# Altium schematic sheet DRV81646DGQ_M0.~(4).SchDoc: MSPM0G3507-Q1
size 431 x 279 mm; Date: Not shown in title block; ApprovedBy: Not shown in title block; CheckedBy: Not shown in title block; Author: Not shown in title block; CompanyName: Not shown in title block; DrawnBy: Mojtaba Afshar; Engineer: Not shown in title block; Organization: Not shown in title block; Address1: Not shown in title block; Address2: Not shown in title block; Address3: Not shown in title block; Address4: Not shown in title block; DocumentNumber: 1; Revision: Use project parameter SCH_Rev; SheetNumber: 2; SheetTotal: 5; PageSetup: Record=PageOptions¦CenterHorizontal=True¦CenterVertical=True¦PrintScale=1.00¦XCorrection=1.00¦YCorrection=1.00¦PrintKind=0¦BorderSize=5000000¦LeftOffset=0¦BottomOffset=0¦Orientation=2¦PaperLength=1000¦PaperWidth=1000¦Scale=100¦PaperSource=15¦PrintQuality=600¦MediaType=1¦DitherType=10¦PaperKind=Letter¦PrintScaleMode=1
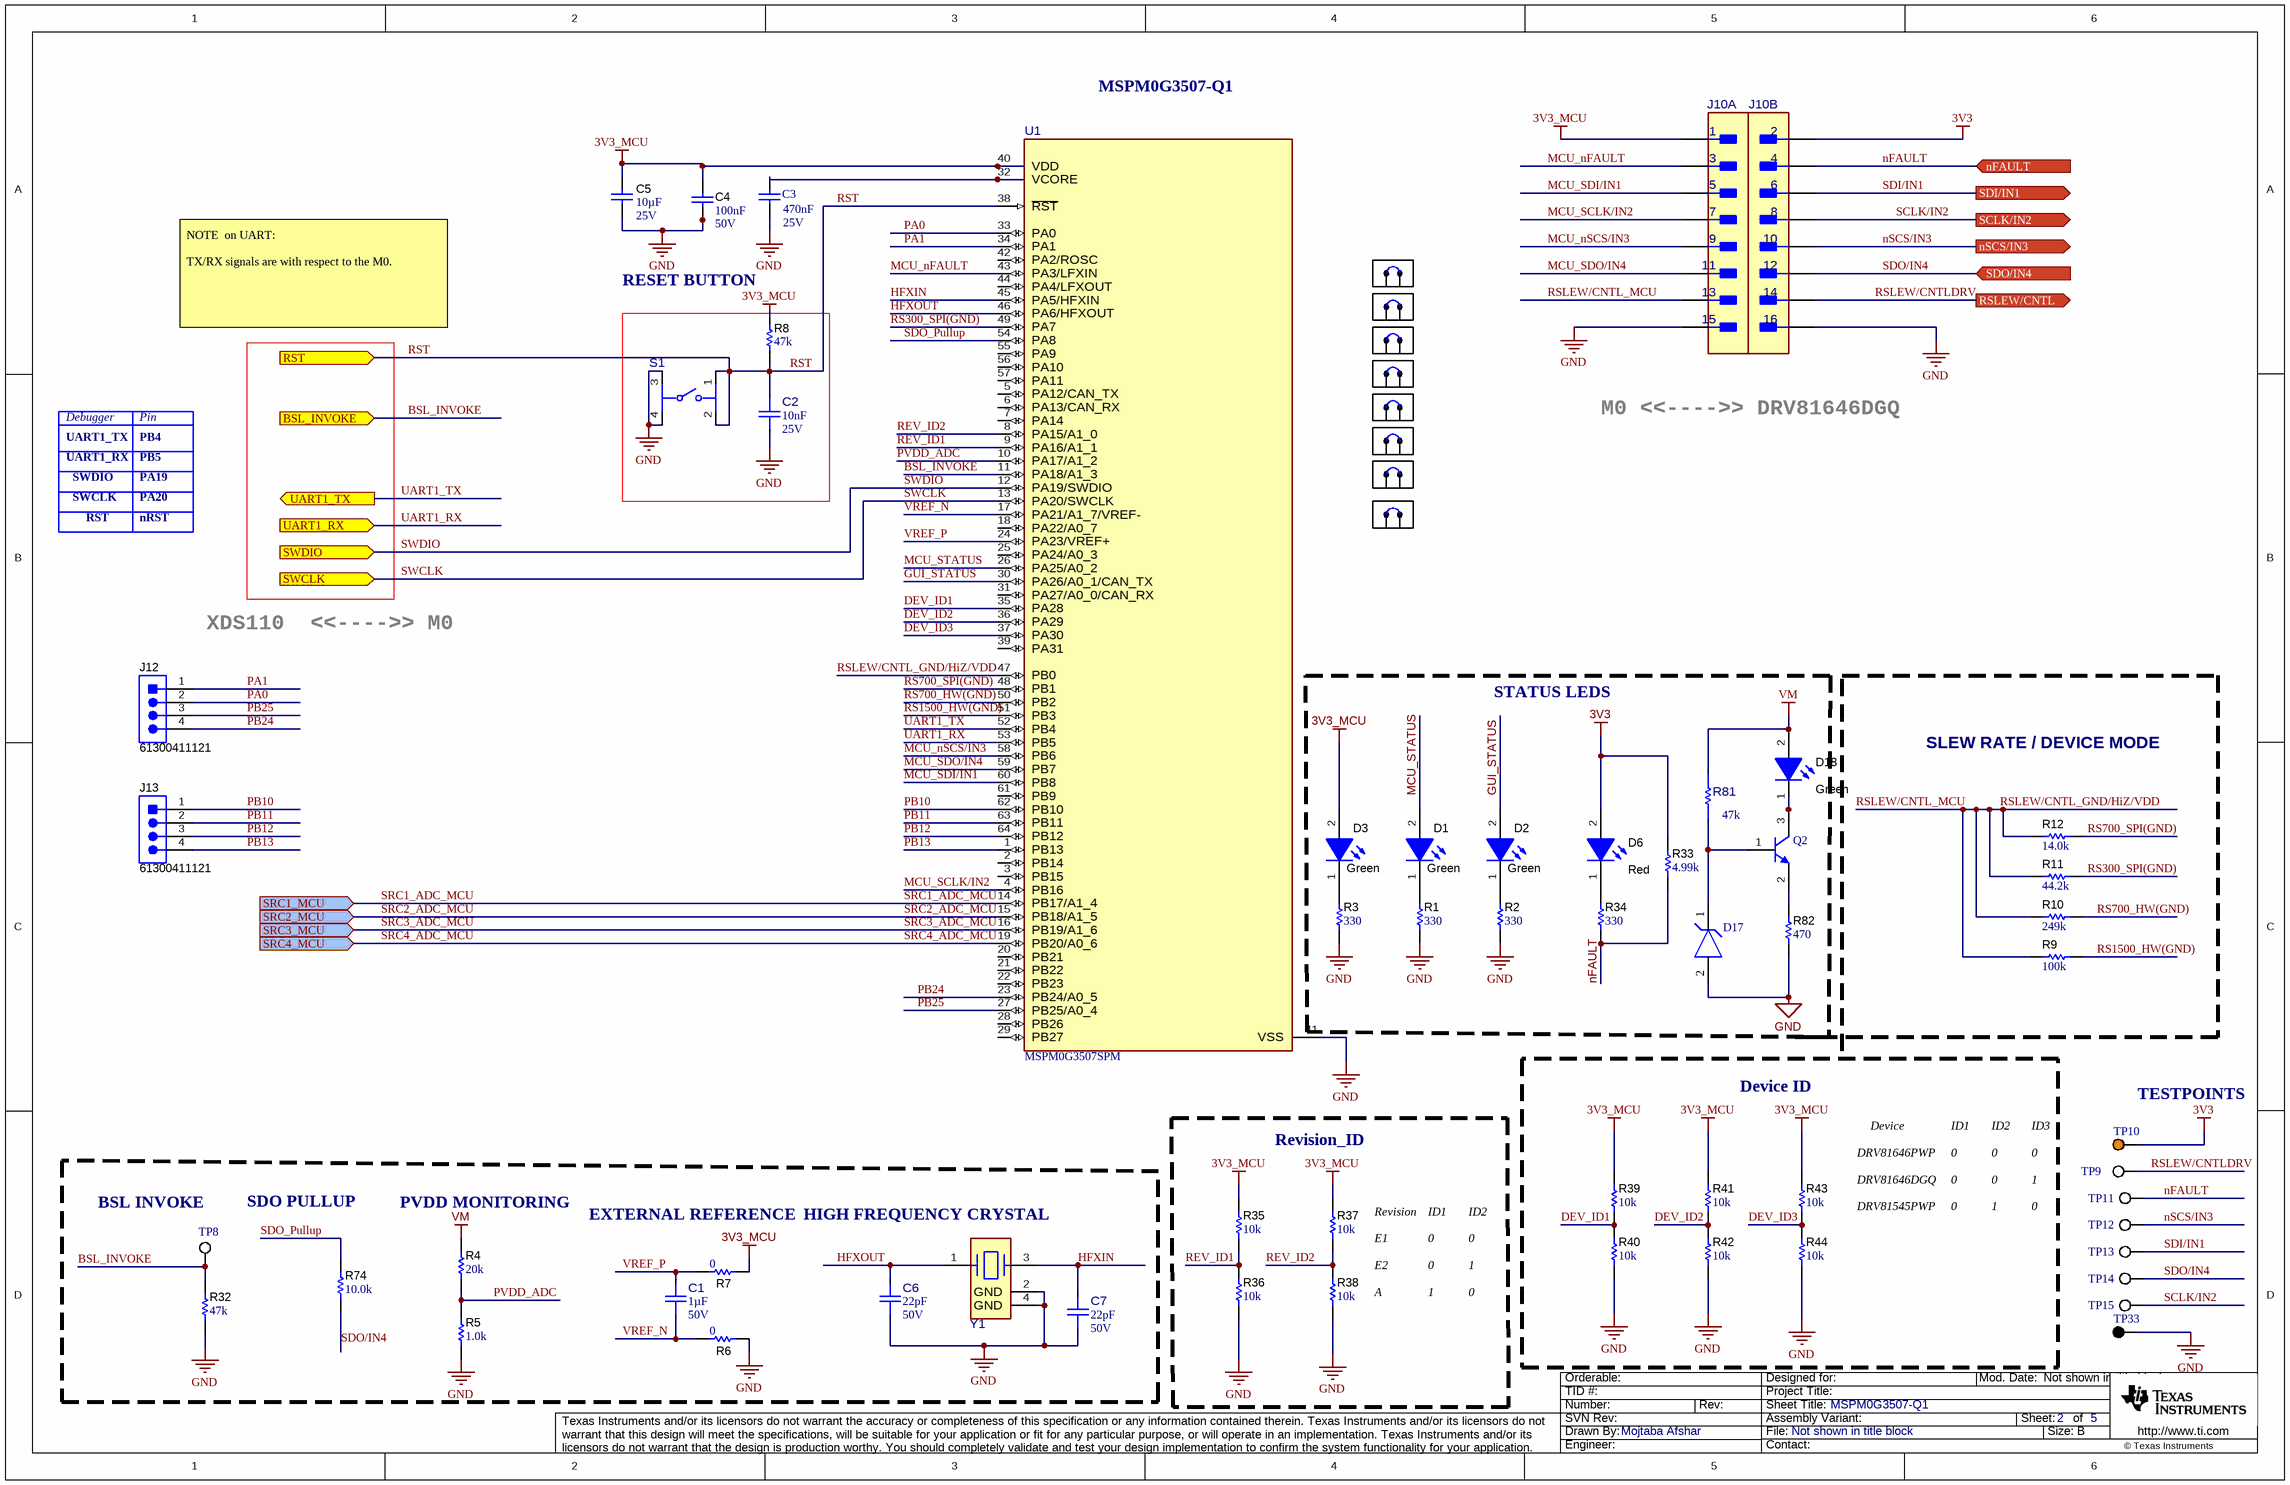
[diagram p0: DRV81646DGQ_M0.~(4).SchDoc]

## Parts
C1  Cap_F: 1µF  VDC_V: 50V  [FP-885012206126_0603-MFG]  (hidden comment: 885012206126)
C2  Cap_F: 10nF  VDC_V: 25V  [FP-885012206065_0603-MFG]  (hidden comment: 885012206065)
C3  value 470nF  Rated Voltage (DC): 25V  [WCAP-CSGP_0603_L1.6W0.8H0.8_Reflow]  (hidden comment: 885012206075R)
C4  Cap_F: 100nF  VDC_V: 50V  [0603]  (hidden comment: 885012206095)
C5  Cap_F: 10µF  VDC_V: 25V  [0603]  (hidden comment: GRM188R61E106KA73D)
C6  ValueDisplayed: 22pF  VDC_V: 50V  [FP-885012005057_0402-MFG]  (hidden comment: 885012005057)
C7  ValueDisplayed: 22pF  VDC_V: 50V  [FP-885012005057_0402-MFG]  (hidden comment: 885012005057)
D1  value Green  [WL-SMCW_GREEN]  (hidden comment: 150060VS75000)
D2  value Green  [WL-SMCW_GREEN]  (hidden comment: 150060VS75000)
D3  value Green  [WL-SMCW_GREEN]  (hidden comment: 150060VS75000)
D6  value Red  [WL-SMCW_RED]  (hidden comment: 150060RS75000)
D17  BZX84J-B4V7,115  [FP-SOD323F-MFG]  (value not drawn)
D18  value Green  [WL-SMCW_GREEN]  (hidden comment: 150060VS75000)
J10  61301621121  [FP-61301621121_HDR16-MFG]  (value not drawn)  (parts A,B of 2)
J12  61300411121  [WURTH_61300411121]
J13  61300411121  [WURTH_61300411121]
Q2  BC846BLT1G  [ONSC-SOT-23-3-318-08_V]  (value not drawn)
R1  ValueDisplayed: 330  [0603]  (hidden comment: RC0603JR-07330RL)
R2  ValueDisplayed: 330  [0603]  (hidden comment: RC0603JR-07330RL)
R3  ValueDisplayed: 330  [0603]  (hidden comment: RC0603JR-07330RL)
R4  ValueDisplayed: 20k  [1210]  (hidden comment: RC1210JR-0720KL)
R5  ValueDisplayed: 1.0k  [0603]  (hidden comment: RC0603JR-071KL)
R6  value 0  [0603]  (hidden comment: Resistor)
R7  value 0  [0603]  (hidden comment: Resistor)
R8  ValueDisplayed: 47k  [0402]  (hidden comment: CRCW040247K0JNED)
R9  ValueDisplayed: 100k  [0603]  (hidden comment: ERJ-3GEYJ104V)
R10  ValueDisplayed: 249k  [0603]  (hidden comment: RC0603FR-07249KL)
R11  ValueDisplayed: 44.2k  [0603]  (hidden comment: RC0603FR-0744K2L)
R12  ValueDisplayed: 14.0k  [0603]  (hidden comment: RC0603FR-0714KL)
R32  ValueDisplayed: 47k  [0402]  (hidden comment: CRCW040247K0JNED)
R33  ValueDisplayed: 4.99k  [0603]  (hidden comment: RC0603FR-074K99L)
R34  ValueDisplayed: 330  [0603]  (hidden comment: RC0603JR-07330RL)
R35  ValueDisplayed: 10k  [0603L]  (hidden comment: RC0603JR-0710KL)
R36  ValueDisplayed: 10k  [0603L]  (hidden comment: RC0603JR-0710KL)
R37  ValueDisplayed: 10k  [0603L]  (hidden comment: RC0603JR-0710KL)
R38  ValueDisplayed: 10k  [0603L]  (hidden comment: RC0603JR-0710KL)
R39  ValueDisplayed: 10k  [0603L]  (hidden comment: RC0603JR-0710KL)
R40  ValueDisplayed: 10k  [0603L]  (hidden comment: RC0603JR-0710KL)
R41  ValueDisplayed: 10k  [0603L]  (hidden comment: RC0603JR-0710KL)
R42  ValueDisplayed: 10k  [0603L]  (hidden comment: RC0603JR-0710KL)
R43  ValueDisplayed: 10k  [0603L]  (hidden comment: RC0603JR-0710KL)
R44  ValueDisplayed: 10k  [0603L]  (hidden comment: RC0603JR-0710KL)
R74  ValueDisplayed: 10.0k  [0603]  (hidden comment: RC0603FR-0710KL)
R81  value 47k  [FP-RCC040247K0FKED_0402-MFG]  (hidden comment: RCC040247K0FKED)
R82  ValueDisplayed: 470  [0603]  (hidden comment: RC0603FR-07470RL)
S1  430481025816  [FP-430481025816_SMT_SW_6MM2_6MM2-MFG]  (value not drawn)
SH-J2  60900213421  [Wurth_60900213421]  (value not drawn)
SH-J3  60900213421  [Wurth_60900213421]  (value not drawn)
SH-J4  60900213421  [Wurth_60900213421]  (value not drawn)
SH-J5  60900213421  [Wurth_60900213421]  (value not drawn)
SH-J6  60900213421  [Wurth_60900213421]  (value not drawn)
SH-J7  60900213421  [Wurth_60900213421]  (value not drawn)
SH-J8  60900213421  [Wurth_60900213421]  (value not drawn)
SH-J9  60900213421  [Wurth_60900213421]  (value not drawn)
TP8  5002  [Keystone5002]  (value not drawn)
TP9  5012  [Keystone5012]  (value not drawn)
TP10  5013  [Keystone5013]  (value not drawn)
TP11  5012  [Keystone5012]  (value not drawn)
TP12  5012  [Keystone5012]  (value not drawn)
TP13  5012  [Keystone5012]  (value not drawn)
TP14  5012  [Keystone5012]  (value not drawn)
TP15  5012  [Keystone5012]  (value not drawn)
TP33  5011  [Keystone5011]  (value not drawn)
U1  MSPM0G3507SPM  [PM0064A-MFG]
Y1  X1E0000210179  [FP-X1E0000210179_TSX-3225-MFG]  (value not drawn)

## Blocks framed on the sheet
STATUS LEDS: D1-D3 D6 D17 D18 Q2 R1-R3 R33 R34 R81 R82
Revision_ID: R35-R38

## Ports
BSL_INVOKE (in), nFAULT (in), nSCS/IN3 (out), RSLEW/CNTL (out), RST (in), SCLK/IN2 (out), SDI/IN1 (out), SDO/IN4 (in), SRC1_MCU (in), SRC2_MCU (in), SRC3_MCU (in), SRC4_MCU (in), SWCLK (in), SWDIO (in), UART1_RX (in), UART1_TX (out)

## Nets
3V3: D6.2(A) J10.2 R33.2 TP10.1
3V3_MCU: C4.1 C5.1 D3.2(A) J10.1 R7.1 R8.2 R35.1 R37.1 R39.1 R41.1 R43.1 U1.40(VDD)
GND: C2.2 C3.1 C4.2 C5.2 C6.1 C7.1 D17.2(A) J10.15 J10.16 R1.1 R2.1 R3.1 R5.1 R6.1 R32.1 R36.2 R38.2 R40.2 R42.2 R44.2 R82.1 S1.3 S1.4 TP33.1 U1.41(VSS) Y1.2(GND) Y1.4(GND)
VM: D18.2(A) R4.2 R81.2
BSL_INVOKE: R32.2 TP8.1 U1.11(PA18/A1_3) ; port BSL_INVOKE
DEV_ID1: R39.2 R40.1 U1.35(PA28)
DEV_ID2: R41.2 R42.1 U1.36(PA29)
DEV_ID3: R43.2 R44.1 U1.37(PA30)
GUI_STATUS: D2.2(A) U1.30(PA26/A0_1/CAN_TX)
HFXIN: C7.2 U1.45(PA5/HFXIN) Y1.3
HFXOUT: C6.2 U1.46(PA6/HFXOUT) Y1.1
MCU_nFAULT: J10.3 U1.43(PA3/LFXIN)
MCU_nSCS/IN3: J10.9 U1.58(PB6)
MCU_SCLK/IN2: J10.7 U1.4(PB16)
MCU_SDI/IN1: J10.5 U1.60(PB8)
MCU_SDO/IN4: J10.11 U1.59(PB7)
MCU_STATUS: D1.2(A) U1.26(PA25/A0_2)
nFAULT: J10.4 R33.1 R34.1 TP11.1 ; port nFAULT
nSCS/IN3: J10.10 TP12.1 ; port nSCS/IN3
PA0: J12.2 U1.33(PA0)
PA1: J12.1 U1.34(PA1)
PB10: J13.1 U1.62(PB10)
PB11: J13.2 U1.63(PB11)
PB12: J13.3 U1.64(PB12)
PB13: J13.4 U1.1(PB13)
PB24: J12.4 U1.23(PB24/A0_5)
PB25: J12.3 U1.27(PB25/A0_4)
PVDD_ADC: R4.1 R5.2 U1.10(PA17/A1_2)
REV_ID1: R35.2 R36.1 U1.9(PA16/A1_1)
REV_ID2: R37.2 R38.1 U1.8(PA15/A1_0)
RS300_SPI(GND): R11.1 U1.49(PA7)
RS700_HW(GND): R10.1 U1.50(PB2)
RS700_SPI(GND): R12.1 U1.48(PB1)
RS1500_HW(GND): R9.1 U1.51(PB3)
RSLEW/CNTL_GND/HiZ/VDD: J10.13 R9.2 R10.2 R11.2 R12.2 U1.47(PB0)  [also labelled RSLEW/CNTL_MCU]
RSLEW/CNTLDRV: J10.14 TP9.1 ; port RSLEW/CNTL
RST: C2.1 R8.1 S1.1 S1.2 U1.38(~{RST}) ; port RST
SCLK/IN2: J10.8 TP15.1 ; port SCLK/IN2
SDI/IN1: J10.6 TP13.1 ; port SDI/IN1
SDO/IN4: J10.12 R74.1 TP14.1 ; port SDO/IN4
SDO_Pullup: R74.2 U1.54(PA8)
SRC1_ADC_MCU: U1.14(PB17/A1_4) ; port SRC1_MCU
SRC2_ADC_MCU: U1.15(PB18/A1_5) ; port SRC2_MCU
SRC3_ADC_MCU: U1.16(PB19/A1_6) ; port SRC3_MCU
SRC4_ADC_MCU: U1.19(PB20/A0_6) ; port SRC4_MCU
SWCLK: U1.13(PA20/SWCLK) ; port SWCLK
SWDIO: U1.12(PA19/SWDIO) ; port SWDIO
UART1_RX: U1.53(PB5) ; port UART1_RX
UART1_TX: U1.52(PB4) ; port UART1_TX
VREF_N: C1.1 R6.2 U1.17(PA21/A1_7/VREF-)
VREF_P: C1.2 R7.2 U1.24(PA23/VREF+)
NetC3_2: C3.2 U1.32(VCORE)
NetD1_1: D1.1(K) R1.2
NetD2_1: D2.1(K) R2.2
NetD3_1: D3.1(K) R3.2
NetD6_1: D6.1(K) R34.2
NetD17_1: D17.1(C) Q2.1(B) R81.1
NetD18_1: D18.1(K) Q2.3(C)
NetQ2_2: Q2.2(E) R82.2

Not connected (* = marked no-connect by the designer): U1 2(PB14) 3(PB15) 5(PA12/CAN_TX) 6(PA13/CAN_RX) 7(PA14) 18(PA22/A0_7) 20(PB21) 21(PB22) 22(PB23) 25(PA24/A0_3) 28(PB26) 29(PB27) 31(PA27/A0_0/CAN_RX) 39(PA31) 42(PA2/ROSC) 44(PA4/LFXOUT) 55(PA9) 56(PA10) 57(PA11) 61(PB9)

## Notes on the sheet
- MSPM0G3507-Q1
- RESET BUTTON
- NOTE  on UART:
  TX/RX signals are with respect to the M0.
- Debugger
- Pin
- M0 <<---->> DRV81646DGQ
- UART1_TX
- UART1_RX
- SWDIO
- SWCLK
- PA19
- PA20
- PB4
- PB5
- RST
- nRST
- XDS110  <<---->> M0
- SLEW RATE / DEVICE MODE
- Device ID
- (near TP10) TESTPOINTS
- DRV81646PWP
- Device
- ID1
- 0
- ID2
- ID3
- (near TP8) BSL INVOKE
- SDO PULLUP
- (near R4) PVDD MONITORING
- EXTERNAL REFERENCE
- HIGH FREQUENCY CRYSTAL
- (near R37) Revision
- DRV81646DGQ
- DRV81545PWP
- 1
- E1
- A
- E2

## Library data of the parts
C1 = CMP-0120896-1: 1 µF ±10% 50V Ceramic Capacitor X7R 0603 (1608 Metric); Manufacturer: Wurth Electronics; AEC Qualified: No; SizeZ_mm: 0.95mm; TempCo: 15%; ValueDisplayed: 1uF; Value: 1µF
C2 = CMP-0120893-1: 10000 pF ±10% 25V Ceramic Capacitor X7R 0603 (1608 Metric); Manufacturer: Wurth Electronics; AEC Qualified: No; SizeZ_mm: 0.87mm; TempCo: 15%; Value: 10nF
C3 = CMP-0119380-1: WCAP-CSGP Multilayer Ceramic Chip Capacitor, General Purpose, size 0603, X7R Class II, 470nF, 25VDC; Manufacturer: Wurth Elektronik; Capacitance Tolerance: +/-10%; Case/Size Code: 0603; Dissipation Factor: 10%; Insulation Resistance: 1.1GOhm; Technical Reference: X7R0603474K025DFCT20000
C4 = CMP-0006837-4: CAP, CERM, 0.1 uF, 50 V, +/- 10%, X7R, 0603; Manufacturer: Wurth Elektronik; TaMin_C: -55°C; Polarized: N; SizeAreaWB_mm2: 4.68; Value1: Unknown; U/M: EA; Value: 0.1uF; TaMax_C: 125°C; SizeZ_mm: 1; SizeX_mm: 1.6; SizeY_mm: 0.8; SizeArea_mm2: 1.28; AEC Category: Q200
C5 = CMP-0860569-1: CAP, CERM, 10 µF, 25 V,+/- 10%, X5R, 0603; Manufacturer: MuRata; TaMin_C: -55°C; Polarized: N; SizeAreaWB_mm2: 4.68; U/M: EA; Value: 10uF; TaMax_C: 85°C; SizeZ_mm: 1; SizeX_mm: 1.6; SizeY_mm: 0.8; SizeArea_mm2: 1.28; AEC Category: Q200
C6 C7 = CMP-0120892-1: 22 pF ±5% 50V Ceramic Capacitor C0G, NP0 0402 (1005 Metric); Manufacturer: Wurth Electronics; AEC Qualified: No; SizeZ_mm: 0.55mm; TempCo: 30ppm/°C; Value: 22pF
D1-D3 D18 = CMP-0002894-2: LED, Green, SMD; Manufacturer: Wurth Elektronik; Type: AlInGaP; Value2: 2V; Io_A: 20mA; Value1: W
D6 = CMP-0002947-3: LED, Red, SMD; Manufacturer: Wurth Elektronik; Value1: 0.072W; Vf_V: 2V; Angle: 140; Tjmax_C: 85°C; Type: AlInGaP; Vr_V: 5V; Io_A: 30mA; Power_TotalModule: 72mW
D17 = CMP-14400-000003-2: DIODE ZENER 4.7V 550MW SOD323F
J10 = CMP-0125672-1: Connector Header Through Hole 16 position 0.100" (2.54mm); Manufacturer: Wurth; ContactFinish: Gold; Current_A: 3A; Row_Count: 2; Voltage_V: 250V; AEC Qualified: No; Conn Gender: Male; Conn Orientation: Straight; SizeZ_mm: 8.89mm
J12 J13 = CMP-0054798-2: Header, 2.54 mm, 4x1, Gold, TH; Manufacturer: Wurth Elektronik; Pitch_mm: 2.54; Gender: Male; Row_Count: 1; Cert_UL: Y; Shrouded: N
Q2 = CMP-1048-00779-1: General Purpose Transistor, NPN Silicon, 3-Pin SOT-23, Pb-Free, Tape and Reel; Manufacturer: On Semiconductor; fT Min (MHz): 100; IC Continuous (A): 0.1
R1-R3 R34 = CMP-0025912-5: RES, 330, 5%, 0.1 W, 0603; Manufacturer: Yageo; Power_W: 100mW; TempCo: 100 ppm/C; Value_Code: 330R; Value: 330; EIA_Code: E24; SizeX_mm: 1.6; SizeY_mm: 0.8; SizeZ_mm: 1; Value2: 0.1W; SizeArea_mm2: 1.28; AEC Qualified: N; VDC_V: 75V; AEC Category: Q200; SizeAreaWB_mm2: 4.68
R4 = CMP-0083496-1: RES, 20 k, 5%, 0.5 W, 1210; Manufacturer: Yageo; Power_W: 500mW; TempCo: 100 ppm/C; SizeAreaWB_mm2: 14.7; Value_Code: 20k0; Value: 20k; EIA_Code: E24; SizeX_mm: 3.2; SizeY_mm: 2.5; SizeZ_mm: 1.35; Value2: 0.5W; SizeArea_mm2: 8; AEC Qualified: N; VDC_V: 200V; AEC Category: Q200
R5 = CMP-0025899-5: RES, 1.0 k, 5%, 0.1 W, 0603; Manufacturer: Yageo; Power_W: 100mW; TempCo: 100 ppm/C; Value_Code: 1k00; Value: 1.0k; EIA_Code: E24; Res_ohm: 1k; SizeX_mm: 1.6; SizeY_mm: 0.8; SizeZ_mm: 1; Value2: 0.1W; SizeArea_mm2: 1.28; AEC Qualified: N; VDC_V: 75V; AEC Category: Q200; SizeAreaWB_mm2: 4.68
R6 R7 = CMP-0025885-5: RES, 0, 5%, 0.1 W, 0603; PartNumber: RC0603JR-070RL; Manufacturer: Yageo; Power_W: 100mW; VDC_V: 75V; AEC Qualified: N; SizeZ_mm: 1; AEC Category: Q200; EIA_Code: E24; SizeArea_mm2: 1.28; SizeAreaWB_mm2: 4.68; SizeX_mm: 1.6; SizeY_mm: 0.8; TempCo: 200 ppm/C; Value2: 0.1W; Value_Code: 0000
R8 R32 = CMP-0026935-3: RES, 47 k, 5%, 0.063 W, AEC-Q200 Grade 0, 0402; Manufacturer: Vishay-Dale; Power_W: 63mW; TempCo: 200 ppm/C; Value_Code: 47k0; Value: 47k; EIA_Code: E24; SizeX_mm: 1; SizeY_mm: 0.5; SizeZ_mm: 0.6; Value2: 0.063W; AEC Qualified: Y; VDC_V: 50V; AEC Category: Q200; AEC Grade: 0
R9 = CMP-0025875-3: RES, 100 k, 5%, 0.1 W, AEC-Q200 Grade 0, 0603; Manufacturer: Panasonic; Power_W: 100mW; TempCo: 200 ppm/C; U/M: EA; Value: 100k; EIA_Code: E24; SizeX_mm: 1.6; SizeY_mm: 0.8; SizeZ_mm: 1; Value2: 0.1W; SizeArea_mm2: 1.28; AEC Qualified: Y; VDC_V: 50V; AEC Grade: 0; AEC Category: Q200
R10 = CMP-0022941-4: RES, 249 k, 1%, 0.1 W, 0603; Manufacturer: Yageo; Power_W: 100mW; TempCo: 100 ppm/C; Value: 249k; EIA_Code: E96; SizeX_mm: 1.6; SizeY_mm: 0.8; SizeZ_mm: 1; Value2: 0.1W; SizeArea_mm2: 1.28; AEC Qualified: N; VDC_V: 75V; AEC Category: Q200; SizeAreaWB_mm2: 4.68
R11 = CMP-0023118-5: RES, 44.2 k, 1%, 0.1 W, 0603; Manufacturer: Yageo; Power_W: 100mW; TempCo: 100 ppm/C; Value_Code: 44k2; Value: 44.2k; EIA_Code: E96; SizeX_mm: 1.6; SizeY_mm: 0.8; SizeZ_mm: 1; Value2: 0.1W; SizeArea_mm2: 1.28; AEC Qualified: N; VDC_V: 75V; AEC Category: Q200; SizeAreaWB_mm2: 4.68
R12 = CMP-0022804-5: RES, 14.0 k, 1%, 0.1 W, 0603; Manufacturer: Yageo; Power_W: 100mW; TempCo: 100 ppm/C; Value_Code: 14k0; Value: 14.0k; EIA_Code: E96; Res_ohm: 14k; SizeX_mm: 1.6; SizeY_mm: 0.8; SizeZ_mm: 1; Value2: 0.1W; SizeArea_mm2: 1.28; AEC Qualified: N; VDC_V: 75V; AEC Category: Q200; SizeAreaWB_mm2: 4.68
R33 = CMP-0023155-5: RES, 4.99 k, 1%, 0.1 W, 0603; Manufacturer: Yageo; Power_W: 100mW; TempCo: 100 ppm/C; Value_Code: 4k99; Value: 4.99k; EIA_Code: E96; SizeX_mm: 1.6; SizeY_mm: 0.8; SizeZ_mm: 1; Value2: 0.1W; SizeArea_mm2: 1.28; AEC Qualified: N; VDC_V: 75V; AEC Category: Q200; SizeAreaWB_mm2: 4.68
R35-R44 = CMP-0025886-5: RES, 10 k, 5%, 0.1 W, 0603; Manufacturer: Yageo; Power_W: 100mW; TempCo: 100 ppm/C; Value_Code: 10k0; Value: 10k; EIA_Code: E24; SizeX_mm: 1.6; SizeY_mm: 0.8; SizeZ_mm: 1; Value2: 0.1W; SizeArea_mm2: 1.28; AEC Qualified: N; VDC_V: 75V; AEC Category: Q200; SizeAreaWB_mm2: 4.68
R74 = CMP-0022746-5: RES, 10.0 k, 1%, 0.1 W, 0603; Manufacturer: Yageo; Power_W: 100mW; TempCo: 100 ppm/C; Value_Code: 10k0; Value: 10.0k; EIA_Code: E96; Res_ohm: 10k; SizeX_mm: 1.6; SizeY_mm: 0.8; SizeZ_mm: 1; Value2: 0.1W; SizeArea_mm2: 1.28; AEC Qualified: N; VDC_V: 75V; AEC Category: Q200; SizeAreaWB_mm2: 4.68
R81 = CMP-0097568-1: 47 kOhms ±1% 0.125W, 1/8W Chip Resistor 0402 (1005 Metric) Automotive AEC-Q200 Thick Film; Manufacturer: Vishay Dale; AEC Grade: Grade 0; SizeZ_mm: 0.4mm; TempCo: 100ppm/°C; AEC Qualified: Yes; Power_W: 125mW; VDC_V: 75V
R82 = CMP-0023129-5: RES, 470, 1%, 0.1 W, 0603; Manufacturer: Yageo; Power_W: 100mW; TempCo: 100 ppm/C; Value_Code: 470R; Value: 470; SizeX_mm: 1.6; SizeY_mm: 0.8; SizeZ_mm: 1; Value2: 0.1W; SizeArea_mm2: 1.28; AEC Qualified: N; VDC_V: 75V; AEC Category: Q200; SizeAreaWB_mm2: 4.68
S1 = CMP-0097347-1: Tactile Switch SPST-NO Top Actuated Surface Mount; Manufacturer: Wurth Electronics; VDC_V: 12V; Electromechanical Life: 1000000Cycles; SizeZ_mm: 2.7mm; Coil Resistance_ohm: 100mΩ; Operating Force: 160gf; AEC Qualified: No; Contact Current Rating: 50mA
SH-J2-SH-J9 = CMP-0003761-2: Shunt, 2.54mm, Gold, Black; Manufacturer: Wurth Elektronik
TP8 = CMP-0055139-2: Test Point, Miniature, White, TH; Manufacturer: Keystone Electronics; ContactFinish: Silver; Green_REACh: Passed; CT: TRUE; Green_Lifecycle: Active; CNHeader: FALSE
TP9 TP11-TP15 = CMP-0055149-2: Test Point, Multipurpose, White, TH; Manufacturer: Keystone Electronics; ContactFinish: Silver; CT: TRUE; CNHeader: FALSE; Green_Lifecycle: Active; Green_REACh: Passed
TP10 = CMP-0055150-1: Test Point, Multipurpose, Orange, TH; Manufacturer: Keystone; CNHeader: FALSE; Green_Lifecycle: Active; Green_REACh: Passed; ContactFinish: Silver; CT: TRUE
TP33 = CMP-0055148-1: Test Point, Multipurpose, Black, TH; Manufacturer: Keystone; CNHeader: FALSE; Green_Lifecycle: Active; Green_REACh: Passed; ContactFinish: Silver; CT: TRUE
U1 = CMP-0093960-1: Mixed-Signal Microcontrollers With CAN-FD Interface LQFP64; Manufacturer: Texas Instruments; Number Of I2C Channels: 2; Frequency_Fixed: 80MHz; Number Of Cores: 1; Number Of Pwm Channels: 14; Data Bus Width: 32bits; Standoff Height: 0.05mm; SizeZ_mm: 1.6mm; Number Of I/Os: 60; Memory Type: FLASH; Min Supply Voltage: 1.62V; Number Of Adc Channels: 16; Memory Size: 128KBytes; TJmax_C: +130°C; Number Of Uart Channels: 4; Number Of Timers/Counters: 7; Max Supply Voltage: 3.6V; TaMin_C: -40°C; Core Architecture: ARM Cortex-M0+; Interface: I2C,SPI,UART,CAN,LIN,IrDA,SMBus; Ram Size: 32KBytes; AEC Qualified: No; TaMax_C: +125°C
Y1 = CMP-0098168-2: Crystal 40MHz ±10ppm (Tol) ±20ppm (Stability) 12pF FUND 40Ohm 4-Pin Mini-CSMD T/R; Manufacturer: Seiko Epson; SizeZ_mm: 0.6mm; AEC Qualified: No; Esr: 40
